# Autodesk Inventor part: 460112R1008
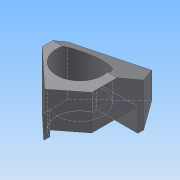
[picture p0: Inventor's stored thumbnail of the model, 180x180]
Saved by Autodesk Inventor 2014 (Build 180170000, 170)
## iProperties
Created: 2016-01
Part Number: 460112R1008
Material: Generic
Document SubType Name: Modeling
Designer: Administrator
Density: 1 g/cm^3
Appearance: Default
Author: Administrator
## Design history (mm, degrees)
sketch "스케치2"
  geometry: L1 (34.842, 55)-(-54, 55); L2 (-54, 55)-(-104.673, 18.184); L3 (-104.673, 18.184)-(-34, -55); L4 (-34, -55)-(9.387, -55); L5 (9.387, -55)-(70, 10); L6 (70, 10)-(34.842, 55); C1 r 39.5 at (0, 0); 1 further point
  constraints: 12 end point, 1 centre point, 1 coincident, 1 horizontal, 1 parallel
  dimensions: "d0" = 79 diameter of C1; "d1" = 124 horizontal distance of L5.end L1.end; "d2" = 104 horizontal distance of L3.end L5.end; "d3" = 110 vertical distance of L1.start L4.end; "d4" = 45 vertical distance of L1.start L5.end; "d5" = 99 deg angle of L5 L6; "d6" = 128 deg angle of L1 L6; "d7" = 134 deg angle of L3 L4; "d8" = 144 deg angle of L1 L2; "d9" = 70 horizontal distance of L5.end point (0, 0); "d10" = 55 distance from line of L1 point (0, 0)
extrude "돌출1" new body sketch "스케치2" distance "d11" = 100; taper "d12" = 0 deg
sketch "스케치3"
  geometry: L1 (104.673, 100)-(34, 100) reference; L2 (104.673, 0)-(34, 0) reference; L3 (34, 0)-(34, 100) reference; L4 (104.673, 100)-(34, 100) reference; L5 (104.673, 0)-(104.673, 100) reference; L6 (-39.5, 100)-(39.5, 100) reference; L7 (104.673, 44.574)-(8.673, 100); L8 (8.673, 100)-(104.673, 100); L9 (104.673, 44.574)-(104.673, 100); 1 further point
  constraints: 6 end point, 2 point on line, 1 collinear, 1 perpendicular
  dimensions: "d13" = 96 distance of L7.end L1.start; "d14" = 30 deg angle of L6 L7
extrude "돌출2" cut sketch "스케치3" stored distance "d15" = 100; taper "d16" = 0 deg
sketch "스케치4"
  geometry: L1 (0, 0)-(88.842, 0) reference; L2 (88.842, 0)-(88.842, 73.83) reference; L3 (-35.158, 0)-(-35.158, 100) reference; L4 (-35.158, 0)-(0, 0) reference; L5 (-35.158, 40)-(78.842, 40); L6 (78.842, 40)-(78.842, 0); 1 further point
  constraints: 4 end point, 2 perpendicular, 2 point on line
  dimensions: "d17" = 114 horizontal distance of L5.start L6.end; "d18" = 40 distance of L3.start L5.start
extrude "돌출3" cut sketch "스케치4" distance "d19" = 70; taper "d20" = 0 deg
node "솔리드1"
node "투영된 루프1"
